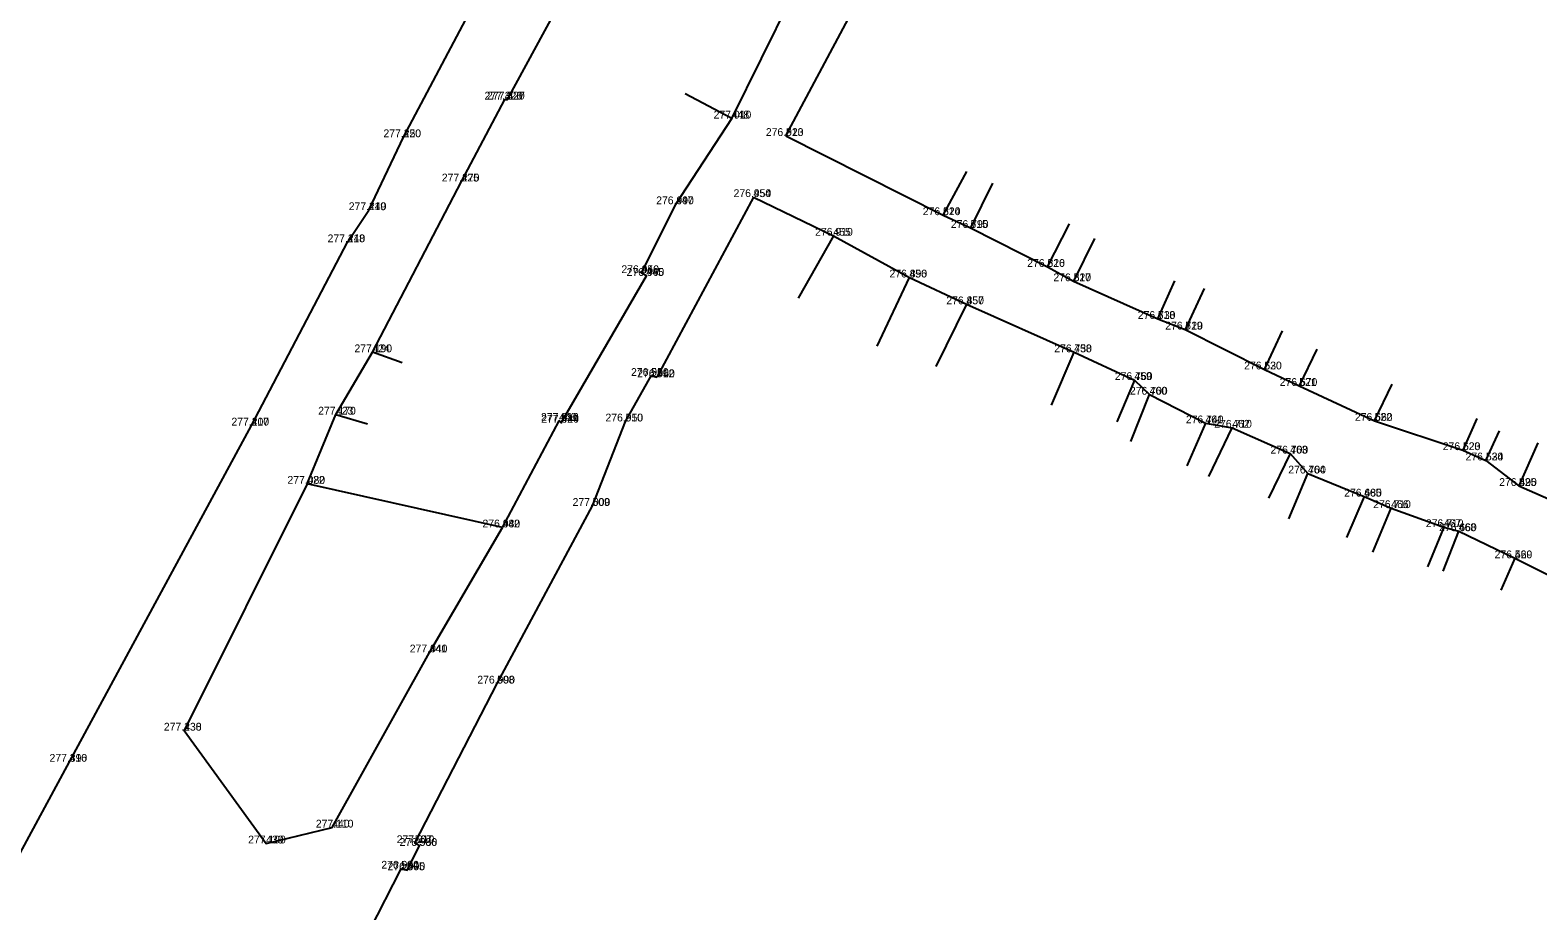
# Model space of a CAD drawing. Extents: x -776701 to -776081, y -974398 to -973771.
# Drawn here: x -776485.83 to -776437.45, y -974080.86 to -974052.6 of the extents above; entities that cross this region are included whole.
import ezdxf

# ---------------------------------------------------------------- set-up
doc = ezdxf.new("R2010")
doc.units = 0
for name, color, linetype in [('1 Body-bod', 7, 'Continuous'), ('11 Rozhrani-nezpev zpev schody', 7, 'Continuous'), ('2 Body-cislo', 7, 'Continuous'), ('3 Body-vyska', 7, 'Continuous'), ('7 Ploty', 7, 'Continuous')]:
    doc.layers.add(name, color=color, linetype=linetype)

msp = doc.modelspace()

# ---------------------------------------------------------------- linework, layer by layer
at = {"layer": '1 Body-bod'}
for p, q in [((-776470.6, -974054.83), (-776470.6, -974054.83)), ((-776470.52, -974054.83), (-776470.52, -974054.83)), ((-776463.32, -974055.44), (-776463.32, -974055.44)), ((-776473.85, -974056.04), (-776473.85, -974056.04)), ((-776461.58, -974056), (-776461.58, -974056)), ((-776471.99, -974057.46), (-776471.99, -974057.46)), ((-776465.11, -974058.19), (-776465.11, -974058.19)), ((-776462.62, -974057.96), (-776462.62, -974057.96)), ((-776474.97, -974058.38), (-776474.97, -974058.38)), ((-776456.54, -974058.54), (-776456.54, -974058.54)), ((-776460.06, -974059.2), (-776460.06, -974059.2)), ((-776455.66, -974058.95), (-776455.66, -974058.95)), ((-776475.65, -974059.41), (-776475.65, -974059.41)), ((-776466.22, -974060.4), (-776466.22, -974060.4)), ((-776466.06, -974060.49), (-776466.06, -974060.49)), ((-776457.62, -974060.54), (-776457.62, -974060.54)), ((-776453.19, -974060.2), (-776453.19, -974060.2)), ((-776452.35, -974060.66), (-776452.35, -974060.66)), ((-776455.79, -974061.4), (-776455.79, -974061.4)), ((-776449.65, -974061.87), (-776449.65, -974061.87)), ((-776448.77, -974062.21), (-776448.77, -974062.21)), ((-776474.85, -974062.94), (-776474.85, -974062.94)), ((-776452.33, -974062.94), (-776452.33, -974062.94)), ((-776446.23, -974063.49), (-776446.23, -974063.49)), ((-776465.91, -974063.7), (-776465.91, -974063.7)), ((-776465.72, -974063.74), (-776465.72, -974063.74)), ((-776450.4, -974063.83), (-776450.4, -974063.83)), ((-776445.11, -974064.02), (-776445.11, -974064.02)), ((-776449.91, -974064.3), (-776449.91, -974064.3)), ((-776476.02, -974064.94), (-776476.02, -974064.94)), ((-776478.73, -974065.29), (-776478.73, -974065.29)), ((-776468.86, -974065.14), (-776468.86, -974065.14)), ((-776468.79, -974065.2), (-776468.79, -974065.2)), ((-776466.73, -974065.16), (-776466.73, -974065.16)), ((-776448.12, -974065.22), (-776448.12, -974065.22)), ((-776447.26, -974065.36), (-776447.26, -974065.36)), ((-776442.69, -974065.14), (-776442.69, -974065.14)), ((-776445.4, -974066.19), (-776445.4, -974066.19)), ((-776439.86, -974066.08), (-776439.86, -974066.08)), ((-776439.12, -974066.41), (-776439.12, -974066.41)), ((-776444.83, -974066.83), (-776444.83, -974066.83)), ((-776476.94, -974067.16), (-776476.94, -974067.16)), ((-776438.06, -974067.23), (-776438.06, -974067.23)), ((-776467.79, -974067.87), (-776467.79, -974067.87)), ((-776443.03, -974067.57), (-776443.03, -974067.57)), ((-776442.16, -974067.94), (-776442.16, -974067.94)), ((-776470.68, -974068.56), (-776470.68, -974068.56)), ((-776440.47, -974068.55), (-776440.47, -974068.55)), ((-776439.99, -974068.68), (-776439.99, -974068.68)), ((-776438.19, -974069.55), (-776438.19, -974069.55)), ((-776473.02, -974072.57), (-776473.02, -974072.57)), ((-776470.85, -974073.57), (-776470.85, -974073.57)), ((-776480.89, -974075.08), (-776480.89, -974075.08)), ((-776484.57, -974076.08), (-776484.57, -974076.08)), ((-776476.14, -974078.19), (-776476.14, -974078.19)), ((-776478.26, -974078.7), (-776478.26, -974078.7)), ((-776473.49, -974078.69), (-776473.49, -974078.69)), ((-776473.34, -974078.78), (-776473.34, -974078.78)), ((-776473.93, -974079.51), (-776473.93, -974079.51)), ((-776473.73, -974079.56), (-776473.73, -974079.56))]:
    msp.add_line(p, q, dxfattribs=at)
at = {"layer": '11 Rozhrani-nezpev zpev schody'}
for points in [[(-776463.32, -974055.44), (-776461.41, -974051.58)], [(-776456.54, -974058.54), (-776455.66, -974058.95)], [(-776460.06, -974059.2), (-776457.62, -974060.54)], [(-776453.19, -974060.2), (-776452.35, -974060.66)], [(-776455.79, -974061.4), (-776452.33, -974062.94)], [(-776449.65, -974061.87), (-776448.77, -974062.21)], [(-776476.02, -974064.94), (-776474.85, -974062.94)], [(-776446.23, -974063.49), (-776445.11, -974064.02)], [(-776450.4, -974063.83), (-776449.91, -974064.3)], [(-776448.12, -974065.22), (-776447.26, -974065.36)], [(-776442.69, -974065.14), (-776439.86, -974066.08)], [(-776445.4, -974066.19), (-776444.83, -974066.83)], [(-776439.12, -974066.41), (-776438.06, -974067.23)], [(-776476.94, -974067.16), (-776480.89, -974075.08), (-776478.26, -974078.7), (-776476.14, -974078.19), (-776473.02, -974072.57), (-776470.68, -974068.56)], [(-776443.03, -974067.57), (-776442.16, -974067.94)], [(-776440.47, -974068.55), (-776439.99, -974068.68)], [(-776438.19, -974069.55), (-776435.57, -974070.85)]]:
    msp.add_lwpolyline(points, dxfattribs=at)
at = {"layer": '7 Ploty'}
for points in [[(-776473.899, -974063.281), (-776474.85, -974062.94), (-776471.99, -974057.46), (-776470.6, -974054.83), (-776470.52, -974054.83), (-776468.72, -974051.51), (-776466.7, -974047.8), (-776465.49, -974045.45), (-776462.51, -974040.03), (-776459.72, -974034.68), (-776457.21, -974036.04)], [(-776489.299, -974079.171), (-776486.95, -974080.48), (-776484.57, -974076.08), (-776478.73, -974065.29), (-776475.65, -974059.41), (-776474.97, -974058.38), (-776473.85, -974056.04), (-776470.9, -974050.46)], [(-776461.58, -974056), (-776459, -974051.14)], [(-776470.68, -974068.56), (-776468.86, -974065.14), (-776468.79, -974065.2), (-776466.06, -974060.49), (-776466.22, -974060.4), (-776465.11, -974058.19), (-776463.32, -974055.44), (-776464.817, -974054.644)], [(-776461.58, -974056), (-776456.54, -974058.54), (-776455.779, -974057.138)], [(-776454.958, -974057.518), (-776455.66, -974058.95), (-776453.19, -974060.2), (-776452.485, -974058.816)], [(-776462.62, -974057.96), (-776465.72, -974063.74)], [(-776462.62, -974057.96), (-776460.06, -974059.2), (-776461.186, -974061.206)], [(-776451.684, -974059.285), (-776452.35, -974060.66), (-776449.65, -974061.87), (-776449.097, -974060.647)], [(-776458.65, -974062.747), (-776457.62, -974060.54), (-776455.79, -974061.4), (-776456.766, -974063.399)], [(-776448.159, -974060.889), (-776448.77, -974062.21), (-776446.23, -974063.49), (-776445.648, -974062.252)], [(-776453.056, -974064.642), (-776452.33, -974062.94), (-776450.4, -974063.83), (-776450.965, -974065.17)], [(-776444.543, -974062.842), (-776445.11, -974064.02), (-776442.69, -974065.14), (-776442.123, -974063.962)], [(-776471.158, -974085.21), (-776471.53, -974085.88), (-776476.01, -974083.57), (-776475.35, -974082.28), (-776475.17, -974082.34), (-776474.79, -974081.6), (-776474.94, -974081.5), (-776473.93, -974079.51), (-776473.73, -974079.56), (-776473.34, -974078.78), (-776473.49, -974078.69), (-776470.85, -974073.57), (-776467.79, -974067.87), (-776466.73, -974065.16), (-776465.91, -974063.7), (-776465.72, -974063.74)], [(-776450.509, -974065.802), (-776449.91, -974064.3), (-776448.12, -974065.22), (-776448.714, -974066.588)], [(-776470.68, -974068.56), (-776476.94, -974067.16), (-776476.02, -974064.94), (-776475.012, -974065.233)], [(-776448.008, -974066.926), (-776447.26, -974065.36), (-776445.4, -974066.19), (-776446.092, -974067.618)], [(-776439.415, -974065.06), (-776439.86, -974066.08), (-776439.12, -974066.41), (-776438.68, -974065.466)], [(-776437.452, -974065.847), (-776438.06, -974067.23), (-776435.47, -974068.36), (-776434.885, -974067.049)], [(-776445.447, -974068.287), (-776444.83, -974066.83), (-776443.03, -974067.57), (-776443.596, -974068.889)], [(-776442.745, -974069.356), (-776442.16, -974067.94), (-776440.47, -974068.55), (-776440.998, -974069.83)], [(-776440.49, -974069.966), (-776439.99, -974068.68), (-776438.19, -974069.55), (-776438.644, -974070.577)]]:
    msp.add_lwpolyline(points, dxfattribs=at)

# ---------------------------------------------------------------- texts
at = {"layer": '2 Body-cislo'}
for s, p in [('426', (-776470.6, -974054.83)), ('427', (-776470.52, -974054.83)), ('448', (-776463.32, -974055.44)), ('420', (-776473.85, -974056.04)), ('513', (-776461.58, -974056)), ('425', (-776471.99, -974057.46)), ('454', (-776462.62, -974057.96)), ('419', (-776474.97, -974058.38)), ('447', (-776465.11, -974058.19)), ('514', (-776456.54, -974058.54)), ('515', (-776455.66, -974058.95)), ('418', (-776475.65, -974059.41)), ('455', (-776460.06, -974059.2)), ('446', (-776466.22, -974060.4)), ('516', (-776453.19, -974060.2)), ('445', (-776466.06, -974060.49)), ('456', (-776457.62, -974060.54)), ('517', (-776452.35, -974060.66)), ('457', (-776455.79, -974061.4)), ('518', (-776449.65, -974061.87)), ('519', (-776448.77, -974062.21)), ('424', (-776474.85, -974062.94)), ('458', (-776452.33, -974062.94)), ('511', (-776465.91, -974063.7)), ('512', (-776465.72, -974063.74)), ('520', (-776446.23, -974063.49)), ('459', (-776450.4, -974063.83)), ('521', (-776445.11, -974064.02)), ('460', (-776449.91, -974064.3)), ('423', (-776476.02, -974064.94)), ('443', (-776468.86, -974065.14)), ('444', (-776468.79, -974065.2)), ('510', (-776466.73, -974065.16)), ('461', (-776448.12, -974065.22)), ('522', (-776442.69, -974065.14)), ('417', (-776478.73, -974065.29)), ('462', (-776447.26, -974065.36)), ('463', (-776445.4, -974066.19)), ('523', (-776439.86, -974066.08)), ('524', (-776439.12, -974066.41)), ('422', (-776476.94, -974067.16)), ('464', (-776444.83, -974066.83)), ('465', (-776443.03, -974067.57)), ('525', (-776438.06, -974067.23)), ('509', (-776467.79, -974067.87)), ('466', (-776442.16, -974067.94)), ('442', (-776470.68, -974068.56)), ('467', (-776440.47, -974068.55)), ('468', (-776439.99, -974068.68)), ('469', (-776438.19, -974069.55)), ('441', (-776473.02, -974072.57)), ('508', (-776470.85, -974073.57)), ('438', (-776480.89, -974075.08)), ('416', (-776484.57, -974076.08)), ('440', (-776476.14, -974078.19)), ('439', (-776478.26, -974078.7)), ('507', (-776473.49, -974078.69)), ('506', (-776473.34, -974078.78)), ('504', (-776473.93, -974079.51)), ('505', (-776473.73, -974079.56))]:
    msp.add_text(s, height=0.25, dxfattribs=at).set_placement(p)
at = {"layer": '3 Body-vyska'}
for s, p in [('277.320', (-776471.252, -974054.83)), ('277.320', (-776471.172, -974054.83)), ('277.010', (-776463.901, -974055.44)), ('277.250', (-776474.496, -974056.04)), ('276.920', (-776462.225, -974056)), ('277.270', (-776472.623, -974057.46)), ('276.950', (-776463.261, -974057.96)), ('277.240', (-776475.609, -974058.38)), ('276.990', (-776465.744, -974058.19)), ('276.820', (-776457.189, -974058.54)), ('276.790', (-776456.288, -974058.95)), ('277.240', (-776476.289, -974059.41)), ('276.910', (-776460.643, -974059.2)), ('276.950', (-776466.861, -974060.4)), ('276.820', (-776453.839, -974060.2)), ('276.960', (-776466.694, -974060.49)), ('276.890', (-776458.258, -974060.54)), ('276.820', (-776452.999, -974060.66)), ('276.850', (-776456.435, -974061.4)), ('276.730', (-776450.291, -974061.87)), ('276.720', (-776449.409, -974062.21)), ('277.190', (-776475.427, -974062.94)), ('276.730', (-776452.971, -974062.94)), ('276.950', (-776466.551, -974063.7)), ('276.960', (-776466.354, -974063.74)), ('276.630', (-776446.877, -974063.49)), ('276.760', (-776451.028, -974063.83)), ('276.670', (-776445.738, -974064.02)), ('276.700', (-776450.542, -974064.3)), ('277.170', (-776476.591, -974064.94)), ('277.010', (-776469.441, -974065.14)), ('277.020', (-776469.433, -974065.2)), ('276.950', (-776467.371, -974065.16)), ('276.740', (-776448.748, -974065.22)), ('276.660', (-776443.324, -974065.14)), ('277.200', (-776479.373, -974065.29)), ('276.710', (-776447.837, -974065.36)), ('276.700', (-776446.032, -974066.19)), ('276.620', (-776440.505, -974066.08)), ('276.530', (-776439.773, -974066.41)), ('277.080', (-776477.576, -974067.16)), ('276.700', (-776445.462, -974066.83)), ('276.680', (-776443.668, -974067.57)), ('276.490', (-776438.694, -974067.23)), ('277.000', (-776468.426, -974067.87)), ('276.710', (-776442.737, -974067.94)), ('276.980', (-776471.318, -974068.56)), ('276.710', (-776441.047, -974068.55)), ('276.660', (-776440.624, -974068.68)), ('276.520', (-776438.842, -974069.55)), ('277.040', (-776473.652, -974072.57)), ('276.990', (-776471.484, -974073.57)), ('277.230', (-776481.542, -974075.08)), ('277.390', (-776485.211, -974076.08)), ('277.110', (-776476.666, -974078.19)), ('277.190', (-776478.837, -974078.7)), ('277.010', (-776474.071, -974078.69)), ('276.980', (-776473.978, -974078.78)), ('276.990', (-776474.564, -974079.51)), ('276.990', (-776474.364, -974079.56))]:
    msp.add_text(s, height=0.25, dxfattribs=at).set_placement(p)

doc.saveas('drawing.dxf')
